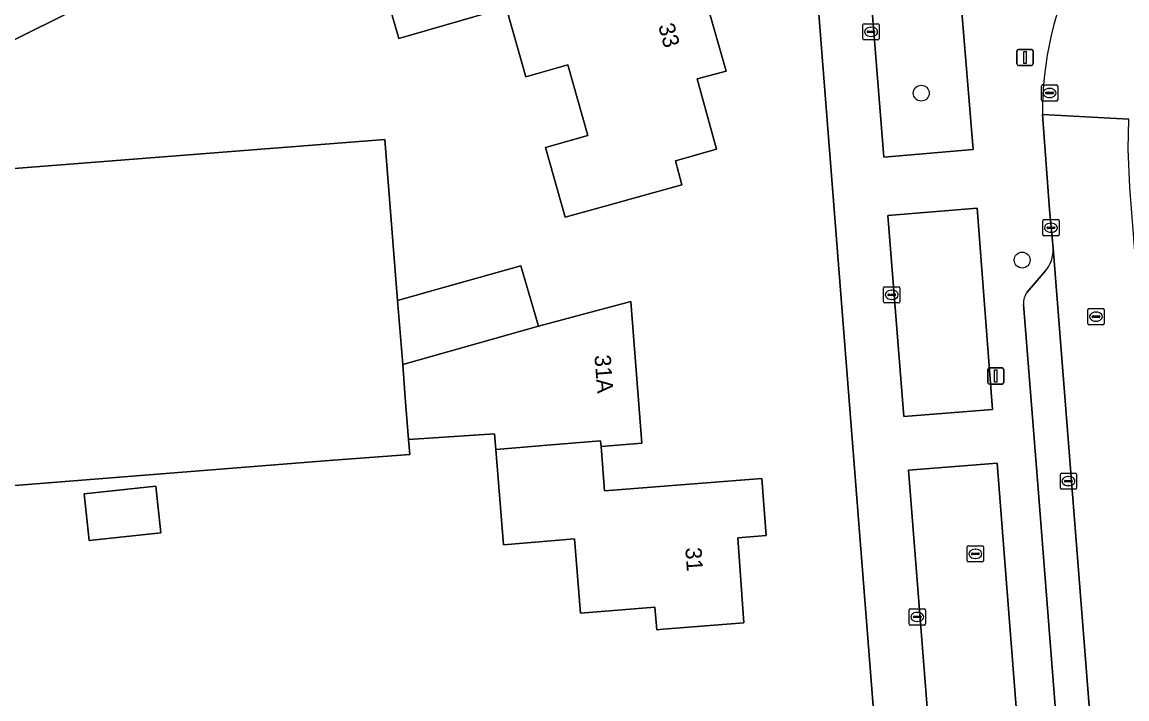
# Model space of a CAD drawing. Extents: x 157793 to 159380, y 380877 to 382313.
# Drawn here: x 158152.9 to 158221.1, y 381384.8 to 381426.6 of the extents above; entities that cross this region are included whole.
import ezdxf

# ---------------------------------------------------------------- set-up
doc = ezdxf.new("R2010")
doc.units = 0
for name, color, linetype in [('IMGEO_Boom', 7, 'Continuous'), ('IMGEO_Brandkraan', 7, 'Continuous'), ('IMGEO_Erf', 7, 'Continuous'), ('IMGEO_Groenvoorziening', 7, 'Continuous'), ('IMGEO_Kolk', 7, 'Continuous'), ('IMGEO_Lichtmast', 7, 'Continuous'), ('IMGEO_Pand', 7, 'Continuous'), ('IMGEO_Pand_nummerreeks', 7, 'Continuous'), ('IMGEO_Parkeervlak_open', 7, 'Continuous'), ('IMGEO_Rijbaan_lokaal_open', 7, 'Continuous'), ('IMGEO_Rioolput', 7, 'Continuous'), ('IMGEO_Voetpad_open', 7, 'Continuous')]:
    doc.layers.add(name, color=color, linetype=linetype)

msp = doc.modelspace()

# ---------------------------------------------------------------- linework, layer by layer
at = {"layer": 'IMGEO_Boom'}
for centre in [(158208.415, 381422.167), (158214.648, 381411.875)]:
    msp.add_circle(centre, 0.489, dxfattribs=at)
at = {"layer": 'IMGEO_Brandkraan'}
for p, q in [((158211.255, 381393.331), (158211.255, 381394.183)), ((158211.33, 381394.257), (158212.182, 381394.257)), ((158211.743, 381394.037), (158211.768, 381394.037)), ((158212.256, 381394.183), (158212.256, 381393.331)), ((158212.182, 381393.257), (158211.33, 381393.257)), ((158211.514, 381393.751), (158211.514, 381393.763)), ((158211.952, 381393.714), (158211.554, 381393.714)), ((158211.557, 381393.8), (158211.955, 381393.8)), ((158211.766, 381393.477), (158211.741, 381393.477)), ((158211.998, 381393.763), (158211.998, 381393.751))]:
    msp.add_line(p, q, dxfattribs=at)
for points in [[(158211.255, 381393.331), (158211.255, 381394.183)], [(158211.33, 381394.257), (158212.182, 381394.257)], [(158212.256, 381394.183), (158212.256, 381393.331)], [(158212.182, 381393.257), (158211.33, 381393.257)]]:
    msp.add_lwpolyline(points, dxfattribs=at)
for centre, radius, start, end in [((158211.332, 381394.181), 0.0765, 91.55205, 178.44795), ((158211.332, 381394.181), 0.0765, 91.55205, 178.44795), ((158212.18, 381394.181), 0.0765, 1.55205, 88.44795), ((158212.18, 381394.181), 0.0765, 1.55205, 88.44795), ((158211.332, 381393.333), 0.0765, 181.55205, 268.44795), ((158211.332, 381393.333), 0.0765, 181.55205, 268.44795), ((158211.554, 381393.76), 0.0403, 85.87752, 175.75265), ((158211.551, 381393.75), 0.0366, 178.93798, 274.71019), ((158211.955, 381393.757), 0.043, 264.86636, 352.45326), ((158211.959, 381393.762), 0.0386, 1.73085, 96.63898), ((158212.18, 381393.333), 0.0765, 271.55205, 358.44795), ((158212.18, 381393.333), 0.0765, 271.55205, 358.44795)]:
    msp.add_arc(centre, radius, start, end, dxfattribs=at)
for centre, major_axis, ratio, start_param, end_param in [((158211.742, 381393.757), (-0.387, 0.002), 0.722429, 4.712389, 7.853982), ((158211.767, 381393.757), (-0.39, 0.002), 0.717154, 1.570796, 4.712389)]:
    msp.add_ellipse(centre, major_axis=major_axis, ratio=ratio, start_param=start_param, end_param=end_param, dxfattribs=at)
at = {"layer": 'IMGEO_Erf'}
for points in [[(158152.732, 381458.23), (158156.81, 381460.268), (158158.66, 381456.564), (158154.582, 381454.526), (158165.775, 381432.125), (158151.804, 381425.141)], [(158194.735, 381429.314), (158196.364, 381423.526), (158194.591, 381423.048), (158195.786, 381418.708), (158193.237, 381417.99), (158193.644, 381416.52), (158190.816, 381415.733), (158188.828, 381415.18), (158186.44, 381414.515), (158185.227, 381418.828), (158187.828, 381419.559), (158186.605, 381423.911), (158184.004, 381423.18), (158182.803, 381427.451), (158176.169, 381425.544), (158174.534, 381431.231)], [(158205.204, 381387.515), (158201.918, 381429.43)], [(158141.903, 381416.705), (158175.301, 381419.308), (158176.093, 381409.379), (158178.92, 381410.175), (158183.704, 381411.522), (158184.786, 381407.806), (158190.495, 381409.33), (158191.166, 381400.576), (158188.649, 381400.383), (158188.859, 381397.638), (158198.579, 381398.399), (158198.843, 381394.888), (158197.095, 381394.735), (158197.472, 381389.511), (158192.489, 381389.104), (158192.088, 381389.071), (158191.974, 381390.466), (158187.389, 381390.091), (158187.014, 381394.675), (158182.628, 381394.317), (158182.147, 381400.197), (158182.069, 381401.152), (158176.776, 381400.809), (158176.849, 381399.892), (158171.864, 381399.508), (158140.559, 381397.031)], [(158124.465, 381365.343), (158154.395, 381367.776), (158156.049, 381347.419), (158179.429, 381349.319), (158181.297, 381326.328), (158181.702, 381321.344), (158200.589, 381322.782), (158204.145, 381323.053), (158210.221, 381323.515), (158205.204, 381387.515)]]:
    msp.add_lwpolyline(points, dxfattribs=at)
msp.add_lwpolyline([(158161.176, 381397.938), (158161.485, 381395.048), (158157.064, 381394.576), (158156.755, 381397.466)], close=True, dxfattribs=at)
at = {"layer": 'IMGEO_Groenvoorziening'}
msp.add_lwpolyline([(158212.863, 381436.273), (158209.685, 381441.047), (158204.381, 381439.799), (158205.057, 381431.35), (158206.108, 381418.23), (158211.612, 381418.687), (158210.856, 381427.931)], dxfattribs=at)
for points in [[(158211.865, 381415.068), (158206.361, 381414.63), (158207.343, 381402.229), (158212.816, 381402.656)], [(158213.093, 381399.346), (158207.619, 381398.923), (158209.561, 381374.348), (158215.01, 381374.789)]]:
    msp.add_lwpolyline(points, close=True, dxfattribs=at)
at = {"layer": 'IMGEO_Kolk'}
for p, q in [((158204.817, 381425.528), (158204.817, 381426.38)), ((158204.892, 381426.454), (158205.744, 381426.454)), ((158205.076, 381425.948), (158205.076, 381425.96)), ((158205.119, 381425.997), (158205.517, 381425.997)), ((158205.305, 381426.234), (158205.33, 381426.234)), ((158205.56, 381425.96), (158205.56, 381425.948)), ((158205.818, 381426.38), (158205.818, 381425.528)), ((158205.744, 381425.454), (158204.892, 381425.454)), ((158205.514, 381425.911), (158205.116, 381425.911)), ((158205.328, 381425.674), (158205.303, 381425.674)), ((158215.995, 381414.37), (158216.847, 381414.37)), ((158215.92, 381413.444), (158215.92, 381414.296)), ((158216.179, 381413.864), (158216.179, 381413.876)), ((158216.617, 381413.827), (158216.219, 381413.827)), ((158216.222, 381413.913), (158216.62, 381413.913)), ((158216.408, 381414.15), (158216.433, 381414.15)), ((158216.663, 381413.876), (158216.663, 381413.864)), ((158216.921, 381414.296), (158216.921, 381413.444)), ((158216.847, 381413.37), (158215.995, 381413.37)), ((158216.431, 381413.59), (158216.406, 381413.59)), ((158206.091, 381409.307), (158206.091, 381410.159)), ((158206.166, 381410.233), (158207.018, 381410.233)), ((158206.35, 381409.727), (158206.35, 381409.739)), ((158206.788, 381409.69), (158206.39, 381409.69)), ((158206.393, 381409.776), (158206.791, 381409.776)), ((158206.579, 381410.013), (158206.604, 381410.013)), ((158206.834, 381409.739), (158206.834, 381409.727)), ((158207.092, 381410.159), (158207.092, 381409.307)), ((158207.018, 381409.233), (158206.166, 381409.233)), ((158206.602, 381409.453), (158206.577, 381409.453)), ((158217.075, 381398.742), (158217.927, 381398.742)), ((158217, 381397.816), (158217, 381398.668)), ((158217.259, 381398.236), (158217.259, 381398.248)), ((158217.697, 381398.199), (158217.299, 381398.199)), ((158217.302, 381398.285), (158217.7, 381398.285)), ((158217.488, 381398.522), (158217.513, 381398.522)), ((158217.743, 381398.248), (158217.743, 381398.236)), ((158218.001, 381398.668), (158218.001, 381397.816)), ((158217.927, 381397.742), (158217.075, 381397.742)), ((158217.511, 381397.962), (158217.486, 381397.962)), ((158207.672, 381389.439), (158207.672, 381390.291)), ((158207.747, 381390.365), (158208.599, 381390.365)), ((158207.931, 381389.859), (158207.931, 381389.871)), ((158208.369, 381389.822), (158207.971, 381389.822)), ((158207.974, 381389.908), (158208.372, 381389.908)), ((158208.16, 381390.145), (158208.185, 381390.145)), ((158208.415, 381389.871), (158208.415, 381389.859)), ((158208.673, 381390.291), (158208.673, 381389.439)), ((158208.599, 381389.365), (158207.747, 381389.365)), ((158208.183, 381389.585), (158208.158, 381389.585))]:
    msp.add_line(p, q, dxfattribs=at)
for points in [[(158204.817, 381425.528), (158204.817, 381426.38)], [(158204.892, 381426.454), (158205.744, 381426.454)], [(158205.818, 381426.38), (158205.818, 381425.528)], [(158205.744, 381425.454), (158204.892, 381425.454)], [(158215.995, 381414.37), (158216.847, 381414.37)], [(158215.92, 381413.444), (158215.92, 381414.296)], [(158216.921, 381414.296), (158216.921, 381413.444)], [(158216.847, 381413.37), (158215.995, 381413.37)], [(158206.091, 381409.307), (158206.091, 381410.159)], [(158206.166, 381410.233), (158207.018, 381410.233)], [(158207.092, 381410.159), (158207.092, 381409.307)], [(158207.018, 381409.233), (158206.166, 381409.233)], [(158217.075, 381398.742), (158217.927, 381398.742)], [(158217, 381397.816), (158217, 381398.668)], [(158218.001, 381398.668), (158218.001, 381397.816)], [(158217.927, 381397.742), (158217.075, 381397.742)], [(158207.672, 381389.439), (158207.672, 381390.291)], [(158207.747, 381390.365), (158208.599, 381390.365)], [(158208.673, 381390.291), (158208.673, 381389.439)], [(158208.599, 381389.365), (158207.747, 381389.365)]]:
    msp.add_lwpolyline(points, dxfattribs=at)
for centre, radius, start, end in [((158204.894, 381426.378), 0.0765, 91.55205, 178.44795), ((158204.894, 381426.378), 0.0765, 91.55205, 178.44795), ((158205.116, 381425.957), 0.0403, 85.87752, 175.75265), ((158205.521, 381425.959), 0.0386, 1.73085, 96.63898), ((158205.742, 381426.378), 0.0765, 1.55205, 88.44795), ((158205.742, 381426.378), 0.0765, 1.55205, 88.44795), ((158204.894, 381425.53), 0.0765, 181.55205, 268.44795), ((158204.894, 381425.53), 0.0765, 181.55205, 268.44795), ((158205.113, 381425.947), 0.0366, 178.93798, 274.71019), ((158205.517, 381425.954), 0.043, 264.86636, 352.45326), ((158205.742, 381425.53), 0.0765, 271.55205, 358.44795), ((158205.742, 381425.53), 0.0765, 271.55205, 358.44795), ((158215.997, 381414.294), 0.0765, 91.55205, 178.44795), ((158215.997, 381414.294), 0.0765, 91.55205, 178.44795), ((158216.845, 381414.294), 0.0765, 1.55205, 88.44795), ((158216.845, 381414.294), 0.0765, 1.55205, 88.44795), ((158216.219, 381413.873), 0.0403, 85.87752, 175.75265), ((158216.216, 381413.863), 0.0366, 178.93798, 274.71019), ((158216.62, 381413.87), 0.043, 264.86636, 352.45326), ((158216.624, 381413.875), 0.0386, 1.73085, 96.63898), ((158215.997, 381413.446), 0.0765, 181.55205, 268.44795), ((158215.997, 381413.446), 0.0765, 181.55205, 268.44795), ((158216.845, 381413.446), 0.0765, 271.55205, 358.44795), ((158216.845, 381413.446), 0.0765, 271.55205, 358.44795), ((158206.168, 381410.157), 0.0765, 91.55205, 178.44795), ((158206.168, 381410.157), 0.0765, 91.55205, 178.44795), ((158206.39, 381409.736), 0.0403, 85.87752, 175.75265), ((158206.387, 381409.726), 0.0366, 178.93798, 274.71019), ((158206.791, 381409.733), 0.043, 264.86636, 352.45326), ((158206.795, 381409.738), 0.0386, 1.73085, 96.63898), ((158207.016, 381410.157), 0.0765, 1.55205, 88.44795), ((158207.016, 381410.157), 0.0765, 1.55205, 88.44795), ((158206.168, 381409.309), 0.0765, 181.55205, 268.44795), ((158206.168, 381409.309), 0.0765, 181.55205, 268.44795), ((158207.016, 381409.309), 0.0765, 271.55205, 358.44795), ((158207.016, 381409.309), 0.0765, 271.55205, 358.44795), ((158217.077, 381398.666), 0.0765, 91.55205, 178.44795), ((158217.077, 381398.666), 0.0765, 91.55205, 178.44795), ((158217.925, 381398.666), 0.0765, 1.55205, 88.44795), ((158217.925, 381398.666), 0.0765, 1.55205, 88.44795), ((158217.299, 381398.245), 0.0403, 85.87752, 175.75265), ((158217.296, 381398.235), 0.0366, 178.93798, 274.71019), ((158217.7, 381398.242), 0.043, 264.86636, 352.45326), ((158217.704, 381398.247), 0.0386, 1.73085, 96.63898), ((158217.077, 381397.818), 0.0765, 181.55205, 268.44795), ((158217.077, 381397.818), 0.0765, 181.55205, 268.44795), ((158217.925, 381397.818), 0.0765, 271.55205, 358.44795), ((158217.925, 381397.818), 0.0765, 271.55205, 358.44795), ((158207.749, 381390.289), 0.0765, 91.55205, 178.44795), ((158207.749, 381390.289), 0.0765, 91.55205, 178.44795), ((158207.971, 381389.868), 0.0403, 85.87752, 175.75265), ((158207.968, 381389.858), 0.0366, 178.93798, 274.71019), ((158208.372, 381389.865), 0.043, 264.86636, 352.45326), ((158208.376, 381389.87), 0.0386, 1.73085, 96.63898), ((158208.597, 381390.289), 0.0765, 1.55205, 88.44795), ((158208.597, 381390.289), 0.0765, 1.55205, 88.44795), ((158207.749, 381389.441), 0.0765, 181.55205, 268.44795), ((158207.749, 381389.441), 0.0765, 181.55205, 268.44795), ((158208.597, 381389.441), 0.0765, 271.55205, 358.44795), ((158208.597, 381389.441), 0.0765, 271.55205, 358.44795)]:
    msp.add_arc(centre, radius, start, end, dxfattribs=at)
for centre, major_axis, ratio, start_param, end_param in [((158205.304, 381425.954), (-0.387, 0.002), 0.722429, 4.712389, 7.853982), ((158205.329, 381425.954), (-0.39, 0.002), 0.717154, 1.570796, 4.712389), ((158216.407, 381413.87), (-0.387, 0.002), 0.722429, 4.712389, 7.853982), ((158216.432, 381413.87), (-0.39, 0.002), 0.717154, 1.570796, 4.712389), ((158206.578, 381409.733), (-0.387, 0.002), 0.722429, 4.712389, 7.853982), ((158206.603, 381409.733), (-0.39, 0.002), 0.717154, 1.570796, 4.712389), ((158217.487, 381398.242), (-0.387, 0.002), 0.722429, 4.712389, 7.853982), ((158217.512, 381398.242), (-0.39, 0.002), 0.717154, 1.570796, 4.712389), ((158208.159, 381389.865), (-0.387, 0.002), 0.722429, 4.712389, 7.853982), ((158208.184, 381389.865), (-0.39, 0.002), 0.717154, 1.570796, 4.712389)]:
    msp.add_ellipse(centre, major_axis=major_axis, ratio=ratio, start_param=start_param, end_param=end_param, dxfattribs=at)
at = {"layer": 'IMGEO_Lichtmast'}
for p, q in [((158214.325, 381423.973), (158214.325, 381424.773)), ((158214.325, 381424.773), (158214.325, 381423.973)), ((158214.425, 381424.873), (158215.215, 381424.873)), ((158215.215, 381424.873), (158214.425, 381424.873)), ((158215.315, 381424.773), (158215.315, 381423.973)), ((158215.315, 381423.973), (158215.315, 381424.773)), ((158215.215, 381423.873), (158214.425, 381423.873)), ((158214.425, 381423.873), (158215.215, 381423.873)), ((158212.52, 381404.324), (158212.52, 381405.124)), ((158212.52, 381405.124), (158212.52, 381404.324)), ((158212.62, 381405.224), (158213.41, 381405.224)), ((158213.41, 381405.224), (158212.62, 381405.224)), ((158213.51, 381405.124), (158213.51, 381404.324)), ((158213.51, 381404.324), (158213.51, 381405.124)), ((158213.41, 381404.224), (158212.62, 381404.224)), ((158212.62, 381404.224), (158213.41, 381404.224))]:
    msp.add_line(p, q, dxfattribs=at)
for points in [[(158214.745, 381424.748), (158214.895, 381424.748), (158214.895, 381423.998), (158214.745, 381423.998), (158214.745, 381424.748)], [(158212.94, 381405.099), (158213.09, 381405.099), (158213.09, 381404.349), (158212.94, 381404.349), (158212.94, 381405.099)]]:
    msp.add_lwpolyline(points, dxfattribs=at)
for centre, start, end in [((158214.425, 381424.773), 90, 180), ((158214.425, 381424.773), 90, 180), ((158215.215, 381424.773), 0, 90), ((158215.215, 381424.773), 360, 90), ((158214.425, 381423.973), 180, 270), ((158214.425, 381423.973), 180, 270), ((158215.215, 381423.973), 270, 0), ((158215.215, 381423.973), 270, 0), ((158212.62, 381405.124), 90, 180), ((158212.62, 381405.124), 90, 180), ((158213.41, 381405.124), 0, 90), ((158213.41, 381405.124), 360, 90), ((158212.62, 381404.324), 180, 270), ((158212.62, 381404.324), 180, 270), ((158213.41, 381404.324), 270, 0), ((158213.41, 381404.324), 270, 0)]:
    msp.add_arc(centre, 0.1, start, end, dxfattribs=at)
at = {"layer": 'IMGEO_Pand'}
for points in [[(158112.296, 381437.92), (158105.266, 381434.42), (158107.949, 381429.043), (158108.81, 381429.501), (158112.381, 381422.33), (158119.541, 381425.901), (158120.403, 381424.174), (158124.878, 381426.406), (158145.928, 381436.906), (158151.804, 381425.141), (158165.775, 381432.125), (158154.582, 381454.526), (158152.732, 381458.23)], [(158194.735, 381429.314), (158192.719, 381428.751), (158192.041, 381431.12), (158192.195, 381431.163), (158190.873, 381435.931), (158190.228, 381435.75), (158176.859, 381432.003), (158176.887, 381431.907), (158174.534, 381431.231), (158176.169, 381425.544), (158182.803, 381427.451), (158184.004, 381423.18), (158186.605, 381423.911), (158187.828, 381419.559), (158185.227, 381418.828), (158186.44, 381414.515), (158188.828, 381415.18), (158190.816, 381415.733), (158193.644, 381416.52), (158193.237, 381417.99), (158195.786, 381418.708), (158194.591, 381423.048), (158196.364, 381423.526)], [(158176.093, 381409.379), (158175.301, 381419.308), (158141.903, 381416.705), (158120.95, 381415.079), (158120.968, 381414.685), (158116.258, 381414.299), (158117.06, 381403.905), (158121.78, 381404.269), (158121.815, 381403.825), (158122.472, 381395.532), (158125.206, 381395.774), (158140.559, 381397.031), (158171.864, 381399.508), (158176.849, 381399.892), (158176.776, 381400.809), (158176.571, 381403.381), (158176.407, 381405.433)], [(158176.093, 381409.379), (158176.407, 381405.433), (158184.786, 381407.806), (158183.704, 381411.522), (158178.92, 381410.175)], [(158184.786, 381407.806), (158176.407, 381405.433), (158176.571, 381403.381), (158176.776, 381400.809), (158182.069, 381401.152), (158182.147, 381400.197), (158183.639, 381400.32), (158185.324, 381400.459), (158188.622, 381400.73), (158188.649, 381400.383), (158191.166, 381400.576), (158190.495, 381409.33)], [(158198.579, 381398.399), (158188.859, 381397.638), (158188.649, 381400.383), (158188.622, 381400.73), (158185.324, 381400.459), (158183.639, 381400.32), (158182.147, 381400.197), (158182.628, 381394.317), (158187.014, 381394.675), (158187.389, 381390.091), (158191.974, 381390.466), (158192.088, 381389.071), (158192.489, 381389.104), (158197.472, 381389.511), (158197.095, 381394.735), (158198.843, 381394.888)], [(158161.176, 381397.938), (158156.755, 381397.466), (158157.064, 381394.576), (158161.485, 381395.048)]]:
    msp.add_lwpolyline(points, close=True, dxfattribs=at)
at = {"layer": 'IMGEO_Parkeervlak_open'}
for points in [[(158223.292, 381327.124), (158216.556, 381412.615)], [(158216.071, 381411.182), (158214.955, 381409.89)], [(158214.727, 381409.144), (158215.126, 381404.243), (158215.61, 381398.043), (158217.329, 381376.222), (158217.736, 381371.13), (158217.894, 381369.324), (158218.28, 381364.239), (158220.469, 381336.432), (158220.91, 381330.318)]]:
    msp.add_lwpolyline(points, dxfattribs=at)
for centre, radius, start, end in [((158214.544, 381412.497), 2.015, 319.25327, 3.34986), ((158215.771, 381409.233), 1.048, 141.15491, 184.85564)]:
    msp.add_arc(centre, radius, start, end, dxfattribs=at)
at = {"layer": 'IMGEO_Rijbaan_lokaal_open'}
for points in [[(158224.969, 381369.667), (158224.95, 381369.907), (158224.37, 381376.845), (158221.296, 381416.377), (158221.181, 381418.719), (158221.236, 381420.566), (158215.902, 381420.86), (158216.33, 381414.992), (158216.556, 381412.615), (158223.292, 381327.124), (158223.344, 381326.119), (158223.356, 381325.962), (158227.941, 381266.477), (158228.132, 381263.825), (158228.186, 381263.368), (158228.537, 381258.317), (158228.694, 381256.338), (158228.709, 381256.156), (158229.383, 381247.511), (158234.402, 381247.964)], [(158215.902, 381420.86), (158221.236, 381420.566)]]:
    msp.add_lwpolyline(points, dxfattribs=at)
msp.add_arc((158236.122, 381421.115), 20.221, 152.94635, 180.72199, dxfattribs=at)
at = {"layer": 'IMGEO_Rioolput'}
for p, q in [((158215.835, 381421.755), (158215.835, 381422.607)), ((158215.91, 381422.681), (158216.762, 381422.681)), ((158216.836, 381422.607), (158216.836, 381421.755)), ((158216.094, 381422.175), (158216.094, 381422.187)), ((158216.532, 381422.138), (158216.134, 381422.138)), ((158216.137, 381422.224), (158216.535, 381422.224)), ((158216.346, 381421.901), (158216.321, 381421.901)), ((158216.323, 381422.461), (158216.348, 381422.461)), ((158216.578, 381422.187), (158216.578, 381422.175)), ((158216.762, 381421.681), (158215.91, 381421.681)), ((158218.701, 381407.959), (158218.701, 381408.811)), ((158218.776, 381408.885), (158219.628, 381408.885)), ((158218.96, 381408.379), (158218.96, 381408.391)), ((158219.398, 381408.342), (158219, 381408.342)), ((158219.003, 381408.428), (158219.401, 381408.428)), ((158219.189, 381408.665), (158219.214, 381408.665)), ((158219.444, 381408.391), (158219.444, 381408.379)), ((158219.702, 381408.811), (158219.702, 381407.959)), ((158219.628, 381407.885), (158218.776, 381407.885)), ((158219.212, 381408.105), (158219.187, 381408.105))]:
    msp.add_line(p, q, dxfattribs=at)
for points in [[(158215.835, 381421.755), (158215.835, 381422.607)], [(158215.91, 381422.681), (158216.762, 381422.681)], [(158216.836, 381422.607), (158216.836, 381421.755)], [(158216.762, 381421.681), (158215.91, 381421.681)], [(158218.701, 381407.959), (158218.701, 381408.811)], [(158218.776, 381408.885), (158219.628, 381408.885)], [(158219.702, 381408.811), (158219.702, 381407.959)], [(158219.628, 381407.885), (158218.776, 381407.885)]]:
    msp.add_lwpolyline(points, dxfattribs=at)
for centre, radius, start, end in [((158215.912, 381422.605), 0.0765, 91.55205, 178.44795), ((158215.912, 381422.605), 0.0765, 91.55205, 178.44795), ((158216.76, 381422.605), 0.0765, 1.55205, 88.44795), ((158216.76, 381422.605), 0.0765, 1.55205, 88.44795), ((158216.134, 381422.184), 0.0403, 85.87752, 175.75265), ((158216.131, 381422.174), 0.0366, 178.93798, 274.71019), ((158216.535, 381422.181), 0.043, 264.86636, 352.45326), ((158216.539, 381422.186), 0.0386, 1.73085, 96.63898), ((158215.912, 381421.757), 0.0765, 181.55205, 268.44795), ((158215.912, 381421.757), 0.0765, 181.55205, 268.44795), ((158216.76, 381421.757), 0.0765, 271.55205, 358.44795), ((158216.76, 381421.757), 0.0765, 271.55205, 358.44795), ((158218.778, 381408.809), 0.0765, 91.55205, 178.44795), ((158218.778, 381408.809), 0.0765, 91.55205, 178.44795), ((158219, 381408.388), 0.0403, 85.87752, 175.75265), ((158218.997, 381408.378), 0.0366, 178.93798, 274.71019), ((158219.401, 381408.385), 0.043, 264.86636, 352.45326), ((158219.405, 381408.39), 0.0386, 1.73085, 96.63898), ((158219.626, 381408.809), 0.0765, 1.55205, 88.44795), ((158219.626, 381408.809), 0.0765, 1.55205, 88.44795), ((158218.778, 381407.961), 0.0765, 181.55205, 268.44795), ((158218.778, 381407.961), 0.0765, 181.55205, 268.44795), ((158219.626, 381407.961), 0.0765, 271.55205, 358.44795), ((158219.626, 381407.961), 0.0765, 271.55205, 358.44795)]:
    msp.add_arc(centre, radius, start, end, dxfattribs=at)
for centre, major_axis, ratio, start_param, end_param in [((158216.322, 381422.181), (-0.387, 0.002), 0.722429, 4.712389, 7.853982), ((158216.347, 381422.181), (-0.39, 0.002), 0.717154, 1.570796, 4.712389), ((158219.188, 381408.385), (-0.387, 0.002), 0.722429, 4.712389, 7.853982), ((158219.213, 381408.385), (-0.39, 0.002), 0.717154, 1.570796, 4.712389)]:
    msp.add_ellipse(centre, major_axis=major_axis, ratio=ratio, start_param=start_param, end_param=end_param, dxfattribs=at)
at = {"layer": 'IMGEO_Voetpad_open'}
for points in [[(158210.856, 381427.931), (158211.612, 381418.687), (158206.108, 381418.23), (158205.057, 381431.35), (158204.381, 381439.799), (158199.572, 381438.618)], [(158201.918, 381429.43), (158205.204, 381387.515), (158210.221, 381323.515), (158204.145, 381323.053), (158200.589, 381322.782), (158200.897, 381318.677), (158205.551, 381319.116)], [(158216.556, 381412.615), (158216.33, 381414.992), (158215.902, 381420.86)], [(158214.955, 381409.89), (158216.071, 381411.182)], [(158215.126, 381404.243), (158214.727, 381409.144)], [(158220.91, 381330.318), (158220.469, 381336.432), (158218.28, 381364.239), (158217.894, 381369.324), (158217.736, 381371.13), (158217.329, 381376.222), (158215.61, 381398.043), (158215.126, 381404.243)]]:
    msp.add_lwpolyline(points, dxfattribs=at)
for points in [[(158206.361, 381414.63), (158211.865, 381415.068), (158212.816, 381402.656), (158207.343, 381402.229)], [(158207.619, 381398.923), (158213.093, 381399.346), (158215.01, 381374.789), (158209.561, 381374.348)]]:
    msp.add_lwpolyline(points, close=True, dxfattribs=at)
for centre, radius, start, end in [((158236.122, 381421.115), 20.221, 152.94635, 180.72199), ((158214.544, 381412.497), 2.015, 319.25327, 3.34986), ((158215.771, 381409.233), 1.048, 141.15491, 184.85564)]:
    msp.add_arc(centre, radius, start, end, dxfattribs=at)

# ---------------------------------------------------------------- texts
at = {"layer": 'IMGEO_Pand_nummerreeks'}
for s, rotation, p in [('33', 285.72175, (158192.168, 381426.326)), ('31A', 274.38292, (158188.243, 381406)), ('31', 274.12509, (158193.85, 381394.125))]:
    msp.add_text(s, height=1, rotation=rotation, dxfattribs=at).set_placement(p)

doc.saveas('drawing.dxf')
